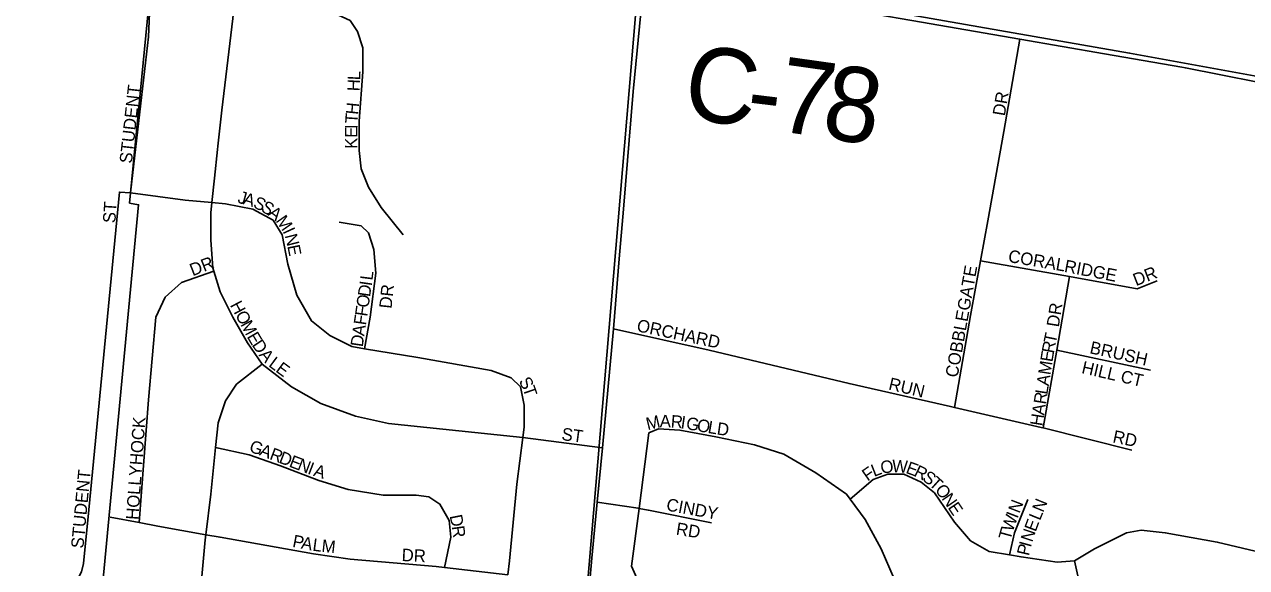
# Model space of a CAD drawing. Extents: x -209 to 4852, y 0 to 905.
# Drawn here: x 505.3 to 523.82, y 252.86 to 261.1 of the extents above; entities that cross this region are included whole.
import ezdxf

# ---------------------------------------------------------------- set-up
doc = ezdxf.new("R2010")
doc.units = 0
for name, color, linetype in [('GM_P_County_Alignment', 7, 'Continuous'), ('GM_X_Airport_Location_Class_2', 7, 'Continuous'), ('GM_X_Airport_Location_Class_3', 7, 'Continuous'), ('GM_X_County_Road_Text', 7, 'Continuous'), ('GM_X_County_Subdivision_Text', 7, 'Continuous'), ('GM_X_Interstate_Location', 7, 'Continuous'), ('GM_X_Minor_River', 7, 'Continuous'), ('GM_X_Township_Text', 7, 'Continuous'), ('GM_X_US_Location', 7, 'Continuous')]:
    doc.layers.add(name, color=color, linetype=linetype)

msp = doc.modelspace()

# ---------------------------------------------------------------- linework, layer by layer
at = {"layer": 'GM_X_Airport_Location_Class_2'}
msp.add_lwpolyline([(505.743, 252.406), (505.876, 252.464), (506.027, 252.594), (506.112, 252.699), (506.163, 252.799), (506.194, 252.922), (506.273, 253.737), (506.739, 258.555), (506.908, 258.542)], dxfattribs=at)
at = {"layer": 'GM_X_County_Road_Text'}
msp.add_lwpolyline([(517.249, 261.412), (518.895, 261.132), (520.387, 260.873), (521.669, 260.651), (522.843, 260.448), (522.897, 260.437), (524.533, 260.114)], dxfattribs=at)
at = {"layer": 'GM_X_County_Subdivision_Text'}
for points in [[(514.314, 257.541), (514.377, 258.296), (514.525, 260.08), (514.663, 261.484), (514.67, 261.564)], [(511.93, 231.62), (511.953, 231.86), (512.017, 232.535), (512.143, 234.083), (512.317, 235.987), (512.505, 237.891), (512.684, 239.704), (512.735, 240.261), (512.847, 241.487), (512.905, 241.98), (513.044, 243.14), (513.202, 244.771), (513.279, 245.714), (513.351, 246.615), (513.473, 248.278), (513.616, 249.917), (513.665, 250.427), (513.698, 250.782), (513.756, 251.389), (513.898, 253.006), (513.981, 253.852), (514.061, 254.677), (514.226, 256.481), (514.314, 257.541)]]:
    msp.add_lwpolyline(points, dxfattribs=at)
at = {"layer": 'GM_X_Minor_River'}
for points in [[(494.708, 264.441), (515.439, 271.658), (513.823, 252.487), (492.971, 244.015)], [(515.439, 271.658), (535.846, 268.527), (534.233, 247.886), (513.823, 252.487)]]:
    msp.add_lwpolyline(points, close=True, dxfattribs=at)
at = {"layer": 'GM_X_Township_Text'}
for points in [[(506.908, 258.542), (507.18, 260.906), (507.248, 262.589)], [(508.232, 259.252), (508.291, 259.795), (508.457, 261.184), (508.594, 262.677)], [(509.742, 262.508), (509.728, 262.443), (509.68, 262.018), (509.624, 261.573), (509.68, 261.406), (509.874, 261.323), (510.235, 261.156), (510.346, 260.99), (510.43, 260.74), (510.43, 260.379), (510.374, 259.628), (510.374, 259.184), (510.402, 258.906), (510.513, 258.628), (510.707, 258.323), (511.04, 257.906)], [(519.396, 255.289), (519.639, 256.684), (519.79, 257.511), (519.902, 258.12), (520.145, 259.475), (520.387, 260.873)], [(514.061, 254.677), (512.853, 254.832), (512.707, 254.851), (510.818, 255.045), (510.318, 255.156), (509.79, 255.35), (509.346, 255.6), (508.902, 255.947), (508.68, 256.267), (508.457, 256.656), (508.263, 257.044), (508.168, 257.353), (508.152, 257.406), (508.124, 257.823), (508.124, 258.239), (508.141, 258.397), (508.18, 258.767), (508.227, 259.202), (508.232, 259.252)], [(512.628, 252.751), (512.652, 252.961), (512.763, 254.128), (512.853, 254.832), (512.874, 254.989), (512.874, 255.323), (512.818, 255.601), (512.679, 255.74), (512.374, 255.85), (511.263, 256.045), (510.452, 256.18), (510.263, 256.211), (509.929, 256.378), (509.652, 256.6), (509.43, 256.989), (509.29, 257.461), (509.207, 257.906), (509.069, 258.128), (508.763, 258.295), (508.346, 258.378), (508.141, 258.397), (507.735, 258.433), (506.908, 258.542)], [(510.452, 256.18), (510.54, 256.656), (510.624, 257.323), (510.596, 257.684), (510.513, 257.934), (510.402, 258.045), (510.069, 258.1)], [(507.038, 253.543), (507.18, 255.406), (507.291, 256.656), (507.43, 256.961), (507.68, 257.183), (508.168, 257.353)], [(519.79, 257.511), (521.141, 257.273), (522.166, 257.089), (522.469, 257.21)], [(520.741, 254.978), (520.946, 256.159), (521.141, 257.273)], [(519.338, 255.302), (519.337, 255.302), (517.799, 255.652), (515.676, 256.158), (514.226, 256.481)], [(520.946, 256.159), (522.369, 255.855)], [(508.902, 255.947), (508.513, 255.641), (508.346, 255.391), (508.235, 255.058), (508.197, 254.684), (508.124, 253.975), (508.05, 253.36), (508.04, 253.28), (507.957, 252.392)], [(522.085, 254.642), (520.741, 254.978), (520.71, 254.986), (519.396, 255.289), (519.338, 255.302)], [(514.618, 253.759), (514.766, 254.904), (514.908, 254.964), (515.231, 254.944), (515.777, 254.843), (516.363, 254.722), (516.808, 254.581), (517.294, 254.298), (517.758, 253.974), (517.814, 253.899), (518.042, 253.59), (518.284, 253.145), (518.547, 252.539), (518.724, 252.184), (519.052, 251.811), (519.477, 251.487), (519.657, 251.441), (520.023, 251.346), (520.832, 251.164), (522.247, 250.841), (523.348, 250.658)], [(511.665, 252.863), (511.763, 253.323), (511.735, 253.573), (511.596, 253.823), (511.429, 253.934), (511.235, 253.961), (510.735, 253.961), (510.207, 254.044), (509.763, 254.183), (509.179, 254.406), (508.707, 254.572), (508.197, 254.684)], [(517.814, 253.899), (518.163, 254.197), (518.385, 254.277), (518.628, 254.277), (518.891, 254.156), (519.093, 253.995), (519.396, 253.55), (519.639, 253.267), (519.922, 253.105), (520.231, 253.054), (520.407, 253.024), (520.953, 252.943), (521.218, 252.965), (521.519, 253.145), (522.005, 253.388), (522.227, 253.429), (522.591, 253.388), (523.379, 253.247), (524.148, 253.065)], [(514.755, 253.731), (514.618, 253.759), (514.604, 253.761), (513.981, 253.852)], [(520.231, 253.054), (520.306, 253.388), (520.508, 253.893)], [(512.628, 252.751), (511.665, 252.863), (511.54, 252.878), (510.235, 252.989), (509.679, 253.072), (508.263, 253.322), (508.05, 253.36), (507.318, 253.489), (507.038, 253.543), (506.596, 253.627)], [(514.618, 253.759), (514.503, 252.882), (514.584, 252.7), (514.725, 252.518), (515.049, 252.397), (515.534, 252.336), (516.08, 252.255)], [(515.716, 253.539), (514.758, 253.731), (514.755, 253.731)], [(522.481, 247.152), (522.752, 247.333), (522.955, 247.555), (523.096, 247.919), (523.137, 248.283), (523.162, 248.582), (523.197, 248.991), (523.247, 249.504), (523.298, 250.042), (523.348, 250.658), (523.4, 251.296), (523.359, 251.599), (523.255, 251.733), (523.218, 251.781), (523.015, 251.922), (522.389, 252.064), (521.661, 252.205), (521.459, 252.306), (521.317, 252.508), (521.218, 252.965)]]:
    msp.add_lwpolyline(points, dxfattribs=at)
at = {"layer": 'GM_X_US_Location'}
for points in [[(505.239, 276.856), (505.907, 276.835), (507.322, 276.623), (508.465, 275.747), (510.473, 277.806), (510.486, 277.327), (512.095, 278.778), (512.354, 278.483), (516.025, 282.023), (516.207, 282.027), (516.009, 279.412), (515.718, 275.598), (515.379, 271.686), (515.077, 268.055), (514.788, 264.427), (514.565, 261.622), (507.308, 262.699), (506.908, 258.542), (506.893, 258.388), (507.029, 258.362), (506.166, 249.27), (505.633, 243.664), (498.996, 241.277)], [(517.801, 261.404), (522.051, 260.662), (524.494, 260.216), (524.814, 263.61)]]:
    msp.add_lwpolyline(points, dxfattribs=at)

# ---------------------------------------------------------------- texts
at = {"layer": 'GM_P_County_Alignment'}
for s, rotation, p in [('C', 350.9823, (515.244, 259.695)), ('7', 351.9862, (516.668, 259.487)), ('8', 350.7387, (517.355, 259.391)), ('-', 353.0877, (516.211, 259.543))]:
    msp.add_text(s, height=1.136, rotation=rotation, dxfattribs=at).set_placement(p)
at = {"layer": 'GM_X_Airport_Location_Class_3'}
for s, rotation, p in [('ST', 86.4262, (506.676, 258.079)), ('STUDENT', 84.6436, (506.192, 253.146))]:
    msp.add_text(s, height=0.1894, rotation=rotation, dxfattribs=at).set_placement(p)
at = {"layer": 'GM_X_Interstate_Location'}
for s, height, rotation, p in [('L', 0.189, 87.2044, (510.387, 260.247)), ('STUDENT', 0.1894, 83.6598, (506.926, 258.981)), ('H', 0.189, 86.9171, (510.378, 260.079)), ('DR', 0.1894, 80.5318, (520.16, 259.7)), ('T', 0.189, 86.2822, (510.347, 259.591)), ('H', 0.189, 84.4177, (510.356, 259.722)), ('I', 0.189, 89.6067, (510.347, 259.51)), ('K', 0.189, 89.6065, (510.345, 259.21)), ('E', 0.189, 89.613, (510.346, 259.377)), ('J', 0.189, 344.7449, (508.52, 258.395)), ('A', 0.189, 343.3971, (508.599, 258.374)), ('S', 0.189, 334.9254, (508.752, 258.329)), ('S', 0.189, 329.3267, (508.869, 258.274)), ('A', 0.189, 322.3914, (508.978, 258.21)), ('M', 0.189, 305.0443, (509.1, 258.119)), ('I', 0.189, 294.8057, (509.21, 257.963)), ('N', 0.189, 284.1105, (509.242, 257.896)), ('E', 0.189, 281.3314, (509.282, 257.737)), ('DR', 0.1894, 21.2528, (507.848, 257.277)), ('CORAL', 0.1894, 350.341, (520.201, 257.496)), ('RIDGE', 0.1894, 348.9599, (521.051, 257.346)), ('L', 0.189, 82.8721, (510.574, 257.209)), ('COBBLEGATE', 0.1894, 79.9201, (519.443, 255.734)), ('DR', 0.1894, 21.2487, (522.148, 257.127)), ('D', 0.189, 81.6811, (510.537, 256.958)), ('I', 0.189, 81.7092, (510.561, 257.123)), ('DR', 0.1894, 83.9832, (510.863, 256.781)), ('O', 0.189, 81.6875, (510.513, 256.793)), ('H', 0.189, 297.9529, (508.41, 256.842)), ('F', 0.189, 81.6937, (510.494, 256.661)), ('DR', 0.1894, 81.0197, (520.978, 256.499)), ('O', 0.189, 297.9562, (508.489, 256.695)), ('M', 0.189, 297.9455, (508.567, 256.548)), ('F', 0.189, 81.6937, (510.474, 256.529)), ('ORCHARD', 0.1894, 348.0236, (514.569, 256.446)), ('E', 0.189, 300.2044, (508.664, 256.364)), ('A', 0.189, 81.6811, (510.45, 256.364)), ('T', 0.189, 78.2239, (520.93, 256.247)), ('D', 0.189, 304.136, (508.739, 256.237)), ('D', 0.189, 81.6875, (510.426, 256.199)), ('R', 0.189, 79.5713, (520.903, 256.101)), ('BRUSH', 0.1894, 347.4738, (521.436, 256.112)), ('A', 0.189, 309.8063, (508.845, 256.082)), ('L', 0.189, 323.1964, (508.987, 255.921)), ('E', 0.189, 80.9734, (520.882, 255.97)), ('E', 0.189, 323.552, (509.094, 255.841)), ('M', 0.189, 81.0018, (520.851, 255.773)), ('HILL CT', 0.1894, 347.0038, (521.313, 255.811)), ('S', 0.189, 299.3518, (512.786, 255.687)), ('RUN', 0.1894, 346.6765, (518.386, 255.562)), ('A', 0.189, 81.0012, (520.825, 255.608)), ('T', 0.189, 288.746, (512.848, 255.58)), ('R', 0.189, 80.9769, (520.781, 255.328)), ('L', 0.189, 81.0108, (520.804, 255.477)), ('A', 0.189, 81.0012, (520.754, 255.164)), ('HOLLYHOCK', 0.1894, 86.0088, (507.026, 253.58)), ('M', 0.189, 13.5326, (514.746, 254.943)), ('A', 0.189, 359.2568, (514.928, 254.989)), ('R', 0.189, 355.4542, (515.091, 254.987)), ('I', 0.189, 351.6227, (515.238, 254.975)), ('G', 0.189, 349.873, (515.318, 254.963)), ('O', 0.189, 349.7147, (515.482, 254.934)), ('H', 0.189, 81.0012, (520.728, 254.999)), ('ST', 0.1894, 352.3949, (513.433, 254.796)), ('L', 0.189, 350.185, (515.648, 254.904)), ('D', 0.189, 351.9422, (515.786, 254.88)), ('RD', 0.1894, 348.1183, (521.785, 254.762)), ('G', 0.189, 339.1241, (508.691, 254.627)), ('A', 0.189, 339.1037, (508.847, 254.568)), ('R', 0.189, 339.1258, (509.002, 254.508)), ('D', 0.189, 339.1241, (509.143, 254.455)), ('E', 0.189, 339.1018, (509.298, 254.395)), ('N', 0.189, 339.1148, (509.423, 254.348)), ('I', 0.189, 339.1037, (509.579, 254.289)), ('A', 0.189, 342.562, (509.668, 254.255)), ('F', 0.189, 34.9405, (518.079, 254.163)), ('L', 0.189, 21.4514, (518.178, 254.234)), ('O', 0.189, 10.4182, (518.293, 254.28)), ('W', 0.189, 356.3157, (518.445, 254.31)), ('E', 0.189, 339.8372, (518.647, 254.299)), ('R', 0.189, 334.1191, (518.768, 254.255)), ('S', 0.189, 324.0208, (518.895, 254.194)), ('T', 0.189, 317.9965, (518.999, 254.119)), ('O', 0.189, 308.3082, (519.092, 254.036)), ('N', 0.189, 304.6841, (519.193, 253.908)), ('CINDY', 0.1894, 349.4614, (515.018, 253.729)), ('E', 0.189, 304.372, (519.288, 253.771)), ('N', 0.189, 68.9374, (520.381, 253.673)), ('N', 0.189, 67.6424, (520.742, 253.687)), ('D', 0.189, 281.2628, (511.743, 253.645)), ('W', 0.189, 70.0973, (520.277, 253.393)), ('I', 0.189, 68.9782, (520.351, 253.596)), ('L', 0.189, 67.7521, (520.692, 253.564)), ('R', 0.189, 277.8931, (511.776, 253.484)), ('RD', 0.1894, 351.0327, (515.167, 253.361)), ('T', 0.189, 74.5987, (520.243, 253.268)), ('N', 0.189, 71.7033, (520.575, 253.237)), ('E', 0.189, 69.5175, (520.627, 253.394)), ('P', 0.189, 349.1454, (509.352, 253.176)), ('A', 0.189, 349.1462, (509.483, 253.151)), ('L', 0.189, 352.3861, (509.658, 253.118)), ('M', 0.189, 354.0441, (509.796, 253.1)), ('I', 0.189, 74.4689, (520.554, 253.159)), ('DR', 0.1894, 356.989, (511.013, 252.961)), ('P', 0.189, 77.1037, (520.524, 253.031))]:
    msp.add_text(s, height=height, rotation=rotation, dxfattribs=at).set_placement(p)

doc.saveas('drawing.dxf')
